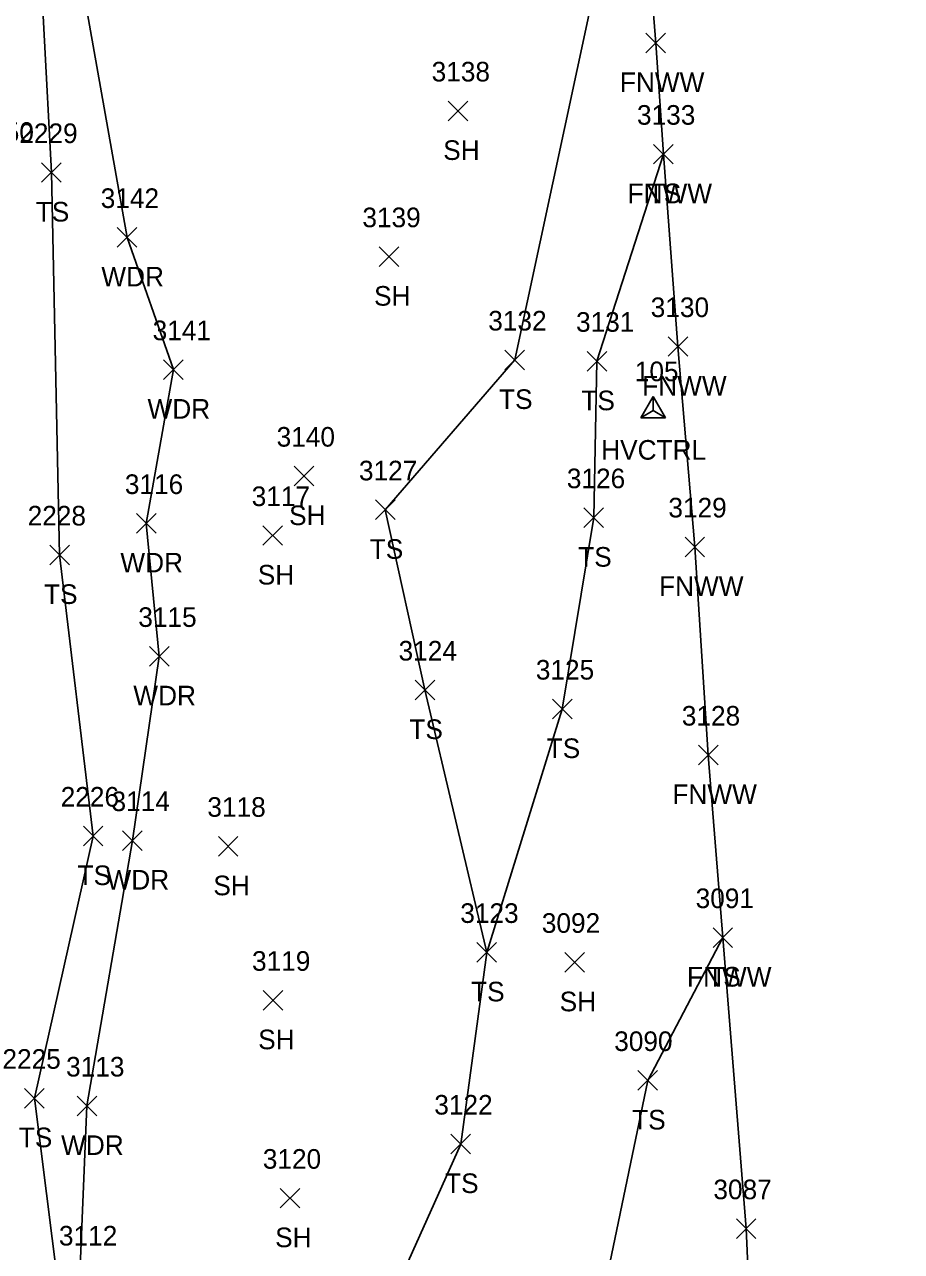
# Model space of a CAD drawing. Extents: x 1650221 to 1650634, y 244606 to 249996.
# Drawn here: x 1650494.9 to 1650584.3, y 245336 to 245461.1 of the extents above; entities that cross this region are included whole.
import ezdxf

# ---------------------------------------------------------------- set-up
doc = ezdxf.new("R2010")
doc.units = 0
for name, color, linetype in [('C_A', 7, 'Continuous'), ('C_I', 7, 'Continuous'), ('CPSM', 7, 'Continuous'), ('L_A', 7, 'Continuous'), ('L_I', 7, 'Continuous'), ('L_TIC', 7, 'Continuous'), ('LAWA', 7, 'Continuous'), ('LELB', 7, 'Continuous'), ('LFNC', 7, 'Continuous'), ('LSOGP', 7, 'Continuous')]:
    doc.layers.add(name, color=color, linetype=linetype)

msp = doc.modelspace()

# ---------------------------------------------------------------- linework, layer by layer
at = {"layer": 'CPSM'}
for p, q in [((1650557.77, 245420.99), (1650559.02, 245423.15)), ((1650560.27, 245420.99), (1650559.02, 245423.15)), ((1650559.02, 245421.71), (1650559.02, 245423.15)), ((1650557.77, 245420.99), (1650559.02, 245421.71)), ((1650557.77, 245420.99), (1650560.27, 245420.99)), ((1650559.02, 245421.71), (1650559.02, 245421.71)), ((1650559.02, 245421.71), (1650560.27, 245420.99))]:
    msp.add_line(p, q, dxfattribs=at)
at = {"layer": 'L_TIC'}
for points in [[(1650558.29, 245458.19), (1650560.29, 245460.19)], [(1650560.29, 245458.19), (1650558.29, 245460.19)], [(1650538.13, 245451.27), (1650540.13, 245453.27)], [(1650540.13, 245451.27), (1650538.13, 245453.27)], [(1650559.06, 245446.86), (1650561.06, 245448.86)], [(1650561.06, 245446.86), (1650559.06, 245448.86)], [(1650559.06, 245446.86), (1650561.06, 245448.86)], [(1650561.06, 245446.86), (1650559.06, 245448.86)], [(1650496.68, 245444.99), (1650498.68, 245446.99)], [(1650498.68, 245444.99), (1650496.68, 245446.99)], [(1650504.4, 245438.37), (1650506.4, 245440.37)], [(1650506.4, 245438.37), (1650504.4, 245440.37)], [(1650531.08, 245436.41), (1650533.08, 245438.41)], [(1650533.08, 245436.41), (1650531.08, 245438.41)], [(1650560.55, 245427.25), (1650562.55, 245429.25)], [(1650562.55, 245427.25), (1650560.55, 245429.25)], [(1650543.91, 245425.88), (1650545.91, 245427.88)], [(1650545.91, 245425.88), (1650543.91, 245427.88)], [(1650552.29, 245425.75), (1650554.29, 245427.75)], [(1650554.29, 245425.75), (1650552.29, 245427.75)], [(1650509.12, 245424.89), (1650511.12, 245426.89)], [(1650511.12, 245424.89), (1650509.12, 245426.89)], [(1650522.42, 245414.04), (1650524.42, 245416.04)], [(1650524.42, 245414.04), (1650522.42, 245416.04)], [(1650530.72, 245410.6), (1650532.72, 245412.6)], [(1650532.72, 245410.6), (1650530.72, 245412.6)], [(1650506.35, 245409.21), (1650508.35, 245411.21)], [(1650508.35, 245409.21), (1650506.35, 245411.21)], [(1650551.97, 245409.8), (1650553.97, 245411.8)], [(1650553.97, 245409.8), (1650551.97, 245411.8)], [(1650519.23, 245407.98), (1650521.23, 245409.98)], [(1650521.23, 245407.98), (1650519.23, 245409.98)], [(1650562.27, 245406.82), (1650564.27, 245408.82)], [(1650564.27, 245406.82), (1650562.27, 245408.82)], [(1650497.52, 245406), (1650499.52, 245408)], [(1650499.52, 245406), (1650497.52, 245408)], [(1650507.67, 245395.66), (1650509.67, 245397.66)], [(1650509.67, 245395.66), (1650507.67, 245397.66)], [(1650534.76, 245392.23), (1650536.76, 245394.23)], [(1650536.76, 245392.23), (1650534.76, 245394.23)], [(1650548.76, 245390.29), (1650550.76, 245392.29)], [(1650550.76, 245390.29), (1650548.76, 245392.29)], [(1650563.63, 245385.6), (1650565.63, 245387.6)], [(1650565.63, 245385.6), (1650563.63, 245387.6)], [(1650500.94, 245377.34), (1650502.94, 245379.34)], [(1650502.94, 245377.34), (1650500.94, 245379.34)], [(1650504.94, 245376.88), (1650506.94, 245378.88)], [(1650506.94, 245376.88), (1650504.94, 245378.88)], [(1650514.7, 245376.3), (1650516.7, 245378.3)], [(1650516.7, 245376.3), (1650514.7, 245378.3)], [(1650565.12, 245366.99), (1650567.12, 245368.99)], [(1650567.12, 245366.99), (1650565.12, 245368.99)], [(1650565.12, 245366.99), (1650567.12, 245368.99)], [(1650567.12, 245366.99), (1650565.12, 245368.99)], [(1650541.05, 245365.48), (1650543.05, 245367.48)], [(1650543.05, 245365.48), (1650541.05, 245367.48)], [(1650541.05, 245365.48), (1650543.05, 245367.48)], [(1650543.05, 245365.48), (1650541.05, 245367.48)], [(1650550.01, 245364.47), (1650552.01, 245366.47)], [(1650552.01, 245364.47), (1650550.01, 245366.47)], [(1650519.27, 245360.6), (1650521.27, 245362.6)], [(1650521.27, 245360.6), (1650519.27, 245362.6)], [(1650557.47, 245352.42), (1650559.47, 245354.42)], [(1650559.47, 245352.42), (1650557.47, 245354.42)], [(1650494.95, 245350.61), (1650496.95, 245352.61)], [(1650496.95, 245350.61), (1650494.95, 245352.61)], [(1650500.31, 245349.82), (1650502.31, 245351.82)], [(1650502.31, 245349.82), (1650500.31, 245351.82)], [(1650538.4, 245345.94), (1650540.4, 245347.94)], [(1650540.4, 245345.94), (1650538.4, 245347.94)], [(1650521.01, 245340.42), (1650523.01, 245342.42)], [(1650523.01, 245340.42), (1650521.01, 245342.42)], [(1650567.5, 245337.31), (1650569.5, 245339.31)], [(1650569.5, 245337.31), (1650567.5, 245339.31)]]:
    msp.add_lwpolyline(points, dxfattribs=at)
at = {"layer": 'LAWA'}
msp.add_lwpolyline([(1650513.9, 245133.55), (1650508.2, 245151.8), (1650510.86, 245189.89), (1650507.07, 245214.01), (1650503.94, 245231.1), (1650499.28, 245247.59), (1650497.45, 245280.46), (1650500, 245310.02), (1650503.12, 245318.4), (1650500.57, 245333.59), (1650501.31, 245350.82), (1650505.94, 245377.88), (1650508.67, 245396.66), (1650507.35, 245410.21), (1650510.12, 245425.89), (1650505.4, 245439.37), (1650500.44, 245467.37)], dxfattribs=at)
at = {"layer": 'LELB'}
for points in [[(1650504.95, 245130.46), (1650502.44, 245141.72), (1650499.16, 245156.24), (1650498.93, 245181.82), (1650503.83, 245194.54), (1650500.59, 245204.36), (1650497.12, 245222.6), (1650494.12, 245240.25), (1650494.91, 245258.03), (1650492.2, 245286.73), (1650496.63, 245312.12), (1650498.98, 245327.58), (1650495.95, 245351.61), (1650501.94, 245378.34), (1650498.52, 245407), (1650497.68, 245445.99), (1650496.14, 245475.39), (1650481.11, 245501.15), (1650483.43, 245539.97), (1650491.3, 245600.05), (1650490.9, 245637.99), (1650484.15, 245671.67)], [(1650531.8, 245329.95), (1650539.4, 245346.94), (1650542.05, 245366.48), (1650535.76, 245393.23), (1650531.72, 245411.6), (1650544.91, 245426.88), (1650553.84, 245468.57), (1650557.53, 245481.22)], [(1650542.05, 245366.48), (1650549.76, 245391.29), (1650552.97, 245410.8), (1650553.29, 245426.75), (1650560.06, 245447.86)], [(1650508.2, 245151.8), (1650523.08, 245163.85), (1650545.23, 245176.29), (1650552.21, 245210.48), (1650551.49, 245242.37), (1650552.52, 245268.33), (1650552.36, 245288), (1650560.92, 245303.66), (1650560.08, 245327.55), (1650553.73, 245330.55), (1650558.47, 245353.42), (1650566.12, 245367.99)]]:
    msp.add_lwpolyline(points, dxfattribs=at)
at = {"layer": 'LFNC'}
msp.add_lwpolyline([(1650584.33, 245116.87), (1650580.12, 245176.92), (1650579.44, 245186.98), (1650578.26, 245204.11), (1650577.83, 245208.68), (1650576.05, 245235.54), (1650574.95, 245249.65), (1650572.25, 245288.19), (1650569.82, 245308.68), (1650568.5, 245338.31), (1650566.12, 245367.99), (1650564.63, 245386.6), (1650563.27, 245407.82), (1650561.55, 245428.25), (1650560.06, 245447.86), (1650559.29, 245459.19), (1650557.53, 245481.22)], dxfattribs=at)
at = {"layer": 'LSOGP'}
msp.add_lwpolyline([(1650584.33, 245116.87), (1650579.44, 245186.98), (1650578.26, 245204.11), (1650577.83, 245208.68), (1650576.05, 245235.54), (1650574.95, 245249.65), (1650572.25, 245288.19), (1650569.82, 245308.68), (1650568.5, 245338.31), (1650566.12, 245367.99), (1650564.63, 245386.6), (1650563.27, 245407.82), (1650561.55, 245428.25), (1650560.06, 245447.86), (1650559.29, 245459.19), (1650557.53, 245481.22)], dxfattribs=at)

# ---------------------------------------------------------------- texts
at = {"layer": 'C_A'}
msp.add_text('HVCTRL', height=2, dxfattribs=at).set_placement((1650553.72, 245416.71))
at = {"layer": 'C_I'}
msp.add_text('105', height=2, dxfattribs=at).set_placement((1650557.15, 245424.71))
at = {"layer": 'L_A'}
for s, p in [('FNWW', (1650555.63, 245454.19)), ('SH', (1650537.62, 245447.27)), ('FNWW', (1650556.41, 245442.86)), ('TS', (1650558.47, 245442.86)), ('TS', (1650496.09, 245440.99)), ('WDR', (1650502.77, 245434.37)), ('SH', (1650530.57, 245432.41)), ('FNWW', (1650557.9, 245423.25)), ('TS', (1650543.31, 245421.88)), ('TS', (1650551.7, 245421.75)), ('WDR', (1650507.48, 245420.89)), ('SH', (1650521.91, 245410.04)), ('TS', (1650530.13, 245406.6)), ('WDR', (1650504.71, 245405.21)), ('TS', (1650551.38, 245405.8)), ('SH', (1650518.72, 245403.98)), ('FNWW', (1650559.62, 245402.82)), ('TS', (1650496.93, 245402)), ('WDR', (1650506.03, 245391.66)), ('TS', (1650534.17, 245388.23)), ('TS', (1650548.17, 245386.29)), ('FNWW', (1650560.98, 245381.6)), ('TS', (1650500.35, 245373.34)), ('WDR', (1650503.3, 245372.88)), ('SH', (1650514.19, 245372.3)), ('FNWW', (1650562.47, 245362.99)), ('TS', (1650564.53, 245362.99)), ('TS', (1650540.46, 245361.48)), ('TS', (1650540.46, 245361.48)), ('SH', (1650549.49, 245360.47)), ('SH', (1650518.76, 245356.6)), ('TS', (1650556.88, 245348.42)), ('TS', (1650494.36, 245346.61)), ('WDR', (1650498.67, 245345.82)), ('TS', (1650537.81, 245341.94)), ('SH', (1650520.49, 245336.42))]:
    msp.add_text(s, height=2, dxfattribs=at).set_placement(p)
at = {"layer": 'L_I'}
for s, p in [('3138', (1650536.44, 245455.27)), ('3133', (1650557.37, 245450.86)), ('3133', (1650557.37, 245450.86)), ('2450', (1650489.95, 245449.11)), ('2229', (1650494.41, 245448.99)), ('3142', (1650502.71, 245442.37)), ('3139', (1650529.38, 245440.41)), ('3130', (1650558.77, 245431.25)), ('3132', (1650542.21, 245429.88)), ('3131', (1650551.16, 245429.75)), ('3141', (1650508, 245428.89)), ('3140', (1650520.64, 245418.04)), ('3127', (1650529.03, 245414.6)), ('3116', (1650505.17, 245413.21)), ('3126', (1650550.22, 245413.8)), ('3117', (1650518.1, 245411.98)), ('3129', (1650560.57, 245410.82)), ('2228', (1650495.26, 245410)), ('3115', (1650506.54, 245399.66)), ('3124', (1650533.07, 245396.23)), ('3125', (1650547.06, 245394.29)), ('3128', (1650561.94, 245389.6)), ('2226', (1650498.63, 245381.34)), ('3114', (1650503.81, 245380.88)), ('3118', (1650513.58, 245380.3)), ('3091', (1650563.35, 245370.99)), ('3091', (1650563.35, 245370.99)), ('3123', (1650539.36, 245369.48)), ('3123', (1650539.36, 245369.48)), ('3092', (1650547.67, 245368.47)), ('3119', (1650518.13, 245364.6)), ('3090', (1650555.05, 245356.42)), ('2225', (1650492.69, 245354.61)), ('3113', (1650499.18, 245353.82)), ('3122', (1650536.71, 245349.94)), ('3120', (1650519.23, 245344.42)), ('3087', (1650565.16, 245341.31)), ('3112', (1650498.45, 245336.59))]:
    msp.add_text(s, height=2, dxfattribs=at).set_placement(p)

doc.saveas('drawing.dxf')
